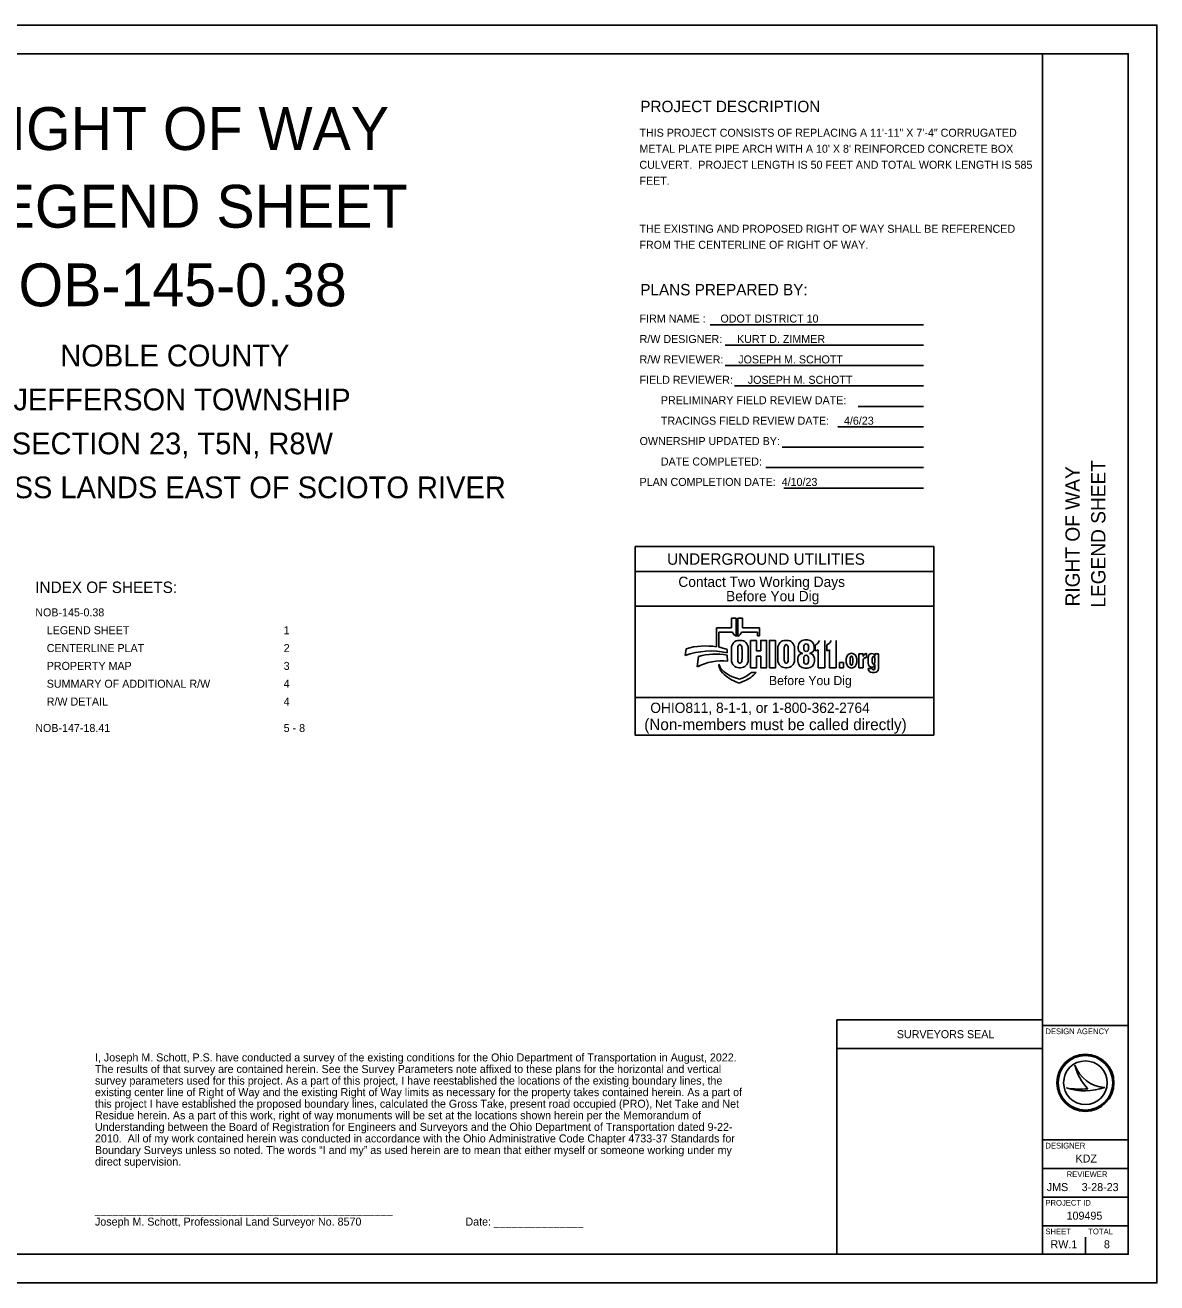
# Model space of a CAD drawing. Extents: x 0 to 34, y 0 to 22.
# Drawn here: x 14.2 to 34, y 0 to 22 of the extents above; entities that cross this region are included whole.
import ezdxf

# ---------------------------------------------------------------- set-up
doc = ezdxf.new("R2010")
doc.units = 0
for name, color, linetype in [('SH_Border', 7, 'Continuous'), ('SH_Cut_Line', 7, 'Continuous'), ('SH_Data', 7, 'Continuous'), ('SH_Text', 7, 'Continuous')]:
    doc.layers.add(name, color=color, linetype=linetype)

msp = doc.modelspace()

# ---------------------------------------------------------------- linework, layer by layer
at = {"layer": 'SH_Border'}
for p, q in [((32, 0.5), (32, 21.5)), ((32, 4.5), (33.5, 4.5)), ((32, 2.5), (33.5, 2.5)), ((32, 2), (33.5, 2)), ((32, 1.5), (33.5, 1.5)), ((32, 1), (33.5, 1))]:
    msp.add_line(p, q, dxfattribs=at)
msp.add_lwpolyline([(1.5, 21.5), (33.5, 21.5), (33.5, 0.5), (1.5, 0.5)], close=True, dxfattribs=at)
at = {"layer": 'SH_Cut_Line'}
msp.add_lwpolyline([(0, 0), (34, 0), (34, 22), (0, 22)], close=True, dxfattribs=at)
at = {"layer": 'SH_Data'}
for p, q in [((26.559, 11.46), (26.296, 11.46)), ((26.296, 11.46), (26.296, 11.125)), ((26.639, 11.626), (26.559, 11.626)), ((26.559, 11.626), (26.559, 11.46)), ((26.639, 11.309), (26.639, 11.626)), ((26.75, 11.626), (26.67, 11.626)), ((26.67, 11.626), (26.67, 11.309)), ((26.75, 11.46), (26.75, 11.626)), ((27.048, 11.46), (26.75, 11.46)), ((27.048, 11.319), (27.048, 11.46)), ((26.334, 11.119), (26.334, 11.383)), ((26.334, 11.383), (26.574, 11.383)), ((26.716, 11.238), (26.691, 11.238)), ((26.735, 11.383), (27.013, 11.383)), ((26.993, 11.237), (26.892, 11.237)), ((26.892, 11.237), (26.892, 10.759)), ((27.013, 11.383), (27.013, 11.319)), ((27.013, 11.319), (27.048, 11.319)), ((27.526, 11.238), (27.502, 11.238)), ((27.887, 11.245), (27.839, 11.245)), ((28.191, 11.237), (28.191, 10.759)), ((28.391, 11.237), (28.391, 10.759)), ((25.761, 11.091), (25.747, 10.974)), ((26.48, 11.023), (26.48, 11.081)), ((26.557, 11.105), (26.557, 10.893)), ((26.666, 10.91), (26.666, 11.092)), ((26.741, 11.092), (26.741, 10.91)), ((26.849, 10.893), (26.849, 11.105)), ((27.368, 11.105), (27.368, 10.893)), ((27.477, 10.91), (27.477, 11.092)), ((27.551, 11.092), (27.551, 10.91)), ((27.66, 10.893), (27.66, 11.105)), ((27.725, 11.131), (27.725, 11.095)), ((27.823, 11.078), (27.823, 11.136)), ((27.904, 11.136), (27.904, 11.078)), ((28.001, 11.095), (28.001, 11.131)), ((28.024, 11.057), (28.024, 11.158)), ((28.073, 10.759), (28.073, 11.071)), ((28.225, 11.057), (28.225, 11.158)), ((28.273, 10.759), (28.273, 11.071)), ((28.86, 11.002), (28.787, 11.002)), ((28.787, 11.002), (28.787, 10.759)), ((28.86, 10.955), (28.86, 11.002)), ((28.921, 11.01), (28.915, 11.01)), ((28.921, 10.936), (28.921, 11.01)), ((29.064, 10.957), (29.064, 11.004)), ((29.064, 11.004), (29.129, 11.004)), ((29.129, 11.004), (29.129, 10.745)), ((25.981, 10.956), (25.959, 10.776)), ((26.333, 10.819), (26.337, 10.792)), ((26.49, 10.873), (26.481, 10.979)), ((26.993, 10.759), (26.993, 10.961)), ((27.719, 10.925), (27.719, 10.874)), ((27.82, 10.865), (27.82, 10.926)), ((27.905, 10.926), (27.905, 10.865)), ((28.007, 10.874), (28.007, 10.925)), ((28.565, 10.85), (28.565, 10.918)), ((28.632, 10.849), (28.632, 10.918)), ((28.68, 10.918), (28.68, 10.849)), ((28.748, 10.918), (28.748, 10.85)), ((28.86, 10.759), (28.86, 10.886)), ((28.909, 10.936), (28.921, 10.936)), ((28.949, 10.837), (28.949, 10.941)), ((29.021, 10.851), (29.021, 10.927)), ((29.064, 10.927), (29.064, 10.851)), ((29.064, 10.745), (29.064, 10.815)), ((26.698, 10.558), (26.609, 10.589)), ((26.691, 10.759), (26.716, 10.759)), ((26.759, 10.585), (26.698, 10.558)), ((26.892, 10.759), (26.993, 10.759)), ((26.991, 10.679), (26.905, 10.679)), ((26.989, 10.676), (26.991, 10.679)), ((27.502, 10.759), (27.526, 10.759)), ((27.84, 10.753), (27.887, 10.753)), ((28.191, 10.759), (28.073, 10.759)), ((28.391, 10.759), (28.273, 10.759)), ((28.787, 10.759), (28.86, 10.759)), ((28.949, 10.745), (29.021, 10.745)), ((29.059, 10.676), (29.019, 10.676)), ((26.633, 10.512), (26.689, 10.488)), ((26.689, 10.488), (26.783, 10.529)), ((30.095, 9.581), (24.87, 9.581)), ((28.4, 4.1), (32, 4.1)), ((32.567, 3.81), (32.567, 3.81)), ((32.417, 3.41), (32.417, 3.41)), ((32.75, 3.5), (32.75, 3.5)), ((33.087, 3.419), (33.087, 3.419)), ((32.375, 0.675), (32.375, 0.675)), ((32.75, 0.5), (32.75, 0.8))]:
    msp.add_line(p, q, dxfattribs=at)
for points in [[(24.87, 12.881), (30.095, 12.881), (30.095, 12.441), (24.87, 12.441)], [(24.87, 12.441), (30.095, 12.441), (30.095, 11.836), (24.87, 11.836)], [(24.87, 11.836), (30.095, 11.836), (30.095, 10.241), (24.87, 10.241)], [(28.449, 10.849), (28.515, 10.849), (28.515, 10.759), (28.449, 10.759)], [(24.87, 10.241), (30.095, 10.241), (30.095, 9.581), (24.87, 9.581)], [(28.4, 4.6), (32, 4.6), (32, 0.5), (28.4, 0.5)]]:
    msp.add_lwpolyline(points, close=True, dxfattribs=at)
for points in [[(26.993, 10.961), (27.07, 10.961), (27.07, 10.759), (27.171, 10.759), (27.171, 11.237), (27.07, 11.237), (27.07, 11.057), (26.993, 11.057), (26.993, 11.237)], [(27.222, 10.759), (27.325, 10.759), (27.325, 11.237), (27.222, 11.237), (27.222, 10.759)], [(27.805, 11.011), (27.805, 11.011)], [(27.921, 11.011), (27.921, 11.011)]]:
    msp.add_lwpolyline(points, dxfattribs=at)
for radius in [0.5, 0.477, 0.477, 0.382]:
    msp.add_circle((32.75, 3.5), radius, dxfattribs=at)
for centre, radius, start, end in [((26.691, 11.105), 0.134, 90, 180), ((26.711, 11.438), 0.147, 201.9296, 240.7469), ((26.598, 11.438), 0.147, 299.2531, 338.0704), ((26.716, 11.105), 0.134, 0, 90), ((27.502, 11.105), 0.134, 90, 180), ((27.526, 11.105), 0.134, 0, 90), ((27.839, 11.131), 0.114, 90, 180), ((27.887, 11.131), 0.114, 0, 90), ((27.974, 11.281), 0.132, 292.5572, 340.7355), ((28.174, 11.281), 0.132, 292.5572, 340.7355), ((26.199, 9.721), 1.332, 77.8238, 109.8274), ((26.105, 9.917), 1.224, 81.0007, 106.3144), ((26.105, 9.917), 1.224, 72.1402, 79.2074), ((27.805, 10.925), 0.0865, 90, 180), ((27.808, 11.095), 0.0837, 180, 268.1442), ((27.918, 11.095), 0.0837, 272.2058, 0), ((27.921, 10.925), 0.0865, 0, 90), ((28.013, 11.188), 0.132, 275.1733, 297.0931), ((28.213, 11.188), 0.132, 275.1733, 297.0931), ((28.661, 10.918), 0.0956, 92.5886, 180), ((28.652, 10.918), 0.0956, 0, 87.4114), ((28.915, 10.955), 0.0548, 90, 180), ((29.018, 10.941), 0.0686, 92.6865, 180), ((29.012, 10.957), 0.0524, 0, 86.9262), ((26.388, 9.929), 0.95, 83.8248, 116.8021), ((26.28, 9.904), 1.094, 79.44, 105.8467), ((26.613, 10.927), 0.3, 201.0457, 232.5314), ((26.548, 10.828), 0.214, 189.6817, 216.0884), ((26.691, 10.893), 0.134, 180, 270), ((26.716, 10.893), 0.134, 270, 0), ((27.502, 10.893), 0.134, 180, 270), ((27.526, 10.893), 0.134, 270, 0), ((27.84, 10.874), 0.121, 180, 270), ((27.887, 10.874), 0.121, 270, 0), ((28.661, 10.85), 0.0956, 180, 267.4114), ((28.652, 10.85), 0.0956, 272.5886, 0), ((28.909, 10.886), 0.0493, 90, 180), ((29.018, 10.837), 0.0692, 180, 265.7132), ((29.017, 10.815), 0.0467, 264.7825, 0), ((26.748, 10.974), 0.461, 216.0884, 235.7167), ((26.9, 11.302), 0.773, 232.5314, 241.794), ((26.997, 11.339), 0.903, 235.7167, 246.2325), ((26.773, 11.065), 0.504, 241.794, 250.9821), ((26.545, 11.078), 0.538, 293.4582, 312.0712), ((26.545, 11.078), 0.599, 293.4582, 317.8286), ((29.019, 10.745), 0.0699, 180, 270), ((29.059, 10.745), 0.0699, 270, 0), ((33.116, 3.998), 0.58, 198.9257, 198.9319), ((33.347, 3.97), 0.796, 191.6379, 191.6421), ((33.116, 3.998), 0.58, 198.9319, 267.1657), ((33.347, 3.97), 0.796, 191.6421, 226.0947), ((32.739, 4.37), 1.013, 251.4576, 290.0832), ((32.648, 4.654), 1.266, 259.4964, 259.4995), ((32.739, 4.37), 1.013, 251.4527, 251.4576), ((32.648, 4.654), 1.266, 259.4995, 276.6672)]:
    msp.add_arc(centre, radius, start, end, dxfattribs=at)
for centre, major_axis, ratio, start_param, end_param in [((26.703, 11.092), (0, 0.0723), 0.514403, 4.712389, 7.853982), ((27.514, 11.092), (0, 0.0723), 0.514403, 4.712389, 7.853982), ((27.864, 11.136), (0.0404, 0), 0.969373, 0, 3.141593), ((27.864, 11.078), (0.0404, 0), 0.818453, 3.141593, 6.283185), ((26.703, 10.91), (0, 0.0723), 0.514403, 1.570796, 4.712389), ((27.514, 10.91), (0, 0.0723), 0.514403, 1.570796, 4.712389), ((27.862, 10.926), (0, 0.0535), 0.794529, 4.712389, 7.853982), ((27.862, 10.865), (0.0425, 0), 0.959837, 3.141593, 6.283185), ((28.656, 10.918), (0, 0.0434), 0.553236, 4.712389, 7.853982), ((28.656, 10.849), (0, 0.046), 0.522014, 1.570796, 4.712389), ((29.043, 10.927), (0, 0.0275), 0.777179, 4.712389, 7.853982), ((29.043, 10.851), (0, 0.0275), 0.777179, 1.570796, 4.712389), ((29.043, 10.745), (0.0214, 0), 0.959012, 3.141593, 6.283185)]:
    msp.add_ellipse(centre, major_axis=major_axis, ratio=ratio, start_param=start_param, end_param=end_param, dxfattribs=at)
at = {"layer": 'SH_Text'}
for p, q in [((26.181, 16.76), (29.918, 16.76)), ((26.445, 16.403), (29.918, 16.403)), ((26.445, 16.046), (29.918, 16.046)), ((26.609, 15.689), (29.918, 15.689)), ((28.773, 15.331), (29.918, 15.331)), ((28.415, 14.974), (29.918, 14.974)), ((27.445, 14.617), (29.918, 14.617)), ((27.16, 14.26), (29.918, 14.26)), ((27.475, 13.903), (29.918, 13.903))]:
    msp.add_line(p, q, dxfattribs=at)

# ---------------------------------------------------------------- texts
at = {"layer": 'SH_Data'}
for s, height, p in [('RIGHT OF WAY', 0.75, (13.21, 19.816)), ('LEGEND SHEET', 0.75, (13.141, 18.457)), ('NOB-145-0.38', 0.75, (13.358, 17.082)), ('NOBLE COUNTY', 0.38, (14.813, 16.03)), ('JEFFERSON TOWNSHIP', 0.38, (13.993, 15.262)), ('SECTION 23, T5N, R8W', 0.38, (13.964, 14.493)), ('CONGRESS LANDS EAST OF SCIOTO RIVER', 0.38, (11.765, 13.725)), ('UNDERGROUND UTILITIES', 0.2, (25.43, 12.561)), ('Contact Two Working Days', 0.18, (25.627, 12.173)), ('INDEX OF SHEETS:', 0.2, (14.375, 12.067)), ('Before You Dig', 0.18, (26.462, 11.923)), ('NOB-145-0.38', 0.14, (14.375, 11.658)), ('LEGEND SHEET', 0.14, (14.575, 11.346)), ('1', 0.14, (18.721, 11.346)), ('CENTERLINE PLAT', 0.14, (14.575, 11.034)), ('2', 0.14, (18.721, 11.034)), ('PROPERTY MAP', 0.14, (14.575, 10.722)), ('3', 0.14, (18.721, 10.722)), ('Before You Dig', 0.15972, (27.213, 10.456)), ('SUMMARY OF ADDITIONAL R/W', 0.14, (14.575, 10.41)), ('4', 0.14, (18.721, 10.41)), ('R/W DETAIL', 0.14, (14.575, 10.098)), ('4', 0.14, (18.721, 10.098)), ('OHIO811, 8-1-1, or 1-800-362-2764', 0.18, (25.136, 9.969)), ('NOB-147-18.41', 0.14, (14.375, 9.636)), ('5 - 8', 0.14, (18.721, 9.636)), ('(Non-members must be called directly)', 0.2, (25.03, 9.668)), ('SURVEYORS SEAL', 0.14, (29.45, 4.28)), ('DESIGN AGENCY', 0.1, (32.05, 4.35)), ('DESIGNER', 0.1, (32.05, 2.35)), ('KDZ', 0.14, (32.577, 2.105)), ('REVIEWER', 0.1, (32.422, 1.85)), ('JMS', 0.14, (32.074, 1.605)), ('3-28-23', 0.14, (32.685, 1.605)), ('PROJECT ID', 0.1, (32.05, 1.35)), ('109495', 0.14, (32.421, 1.105)), ('SHEET', 0.1, (32.05, 0.85)), ('TOTAL', 0.1, (32.8, 0.85)), ('RW.1', 0.14, (32.14, 0.605)), ('8', 0.14, (33.074, 0.605))]:
    msp.add_text(s, height=height, dxfattribs=at).set_placement(p)
for s, p in [('LEGEND SHEET', (33.1, 11.81)), ('RIGHT OF WAY', (32.65, 11.832))]:
    msp.add_text(s, height=0.25, rotation=90, dxfattribs=at).set_placement(p)
at = {"layer": 'SH_Text'}
for s, height, p in [('PROJECT DESCRIPTION', 0.2, (24.961, 20.478)), ('THIS PROJECT CONSISTS OF REPLACING A 11\'-11" X 7\'-4" CORRUGATED ', 0.14, (24.946, 20.048)), ("METAL PLATE PIPE ARCH WITH A 10' X 8' REINFORCED CONCRETE BOX ", 0.14, (24.946, 19.768)), ('CULVERT.  PROJECT LENGTH IS 50 FEET AND TOTAL WORK LENGTH IS 585 ', 0.14, (24.946, 19.488)), ('FEET.', 0.14, (24.946, 19.208)), ('THE EXISTING AND PROPOSED RIGHT OF WAY SHALL BE REFERENCED ', 0.14, (24.946, 18.368)), ('FROM THE CENTERLINE OF RIGHT OF WAY.', 0.14, (24.946, 18.088)), ('PLANS PREPARED BY:', 0.2, (24.961, 17.273)), ('FIRM NAME :     ODOT DISTRICT 10', 0.14, (24.949, 16.797)), ('R/W DESIGNER:     KURT D. ZIMMER', 0.14, (24.949, 16.44)), ('R/W REVIEWER:     JOSEPH M. SCHOTT', 0.14, (24.949, 16.083)), ('FIELD REVIEWER:     JOSEPH M. SCHOTT', 0.14, (24.949, 15.726)), ('PRELIMINARY FIELD REVIEW DATE:', 0.14, (25.321, 15.369)), ('TRACINGS FIELD REVIEW DATE:     4/6/23      ', 0.14, (25.321, 15.011)), ('OWNERSHIP UPDATED BY:', 0.14, (24.949, 14.655)), ('DATE COMPLETED:', 0.14, (25.321, 14.297)), ('PLAN COMPLETION DATE:  4/10/23', 0.14, (24.949, 13.94)), ('I, Joseph M. Schott, P.S. have conducted a survey of the existing conditions for the Ohio Department of Transportation in August, 2022. ', 0.14, (15.419, 3.873)), ('The results of that survey are contained herein. See the Survey Parameters note affixed to these plans for the horizontal and vertical ', 0.14, (15.419, 3.671)), ('survey parameters used for this project. As a part of this project, I have reestablished the locations of the existing boundary lines, the ', 0.14, (15.419, 3.468)), ('existing center line of Right of Way and the existing Right of Way limits as necessary for the property takes contained herein. As a part of ', 0.14, (15.419, 3.266)), ('this project I have established the proposed boundary lines, calculated the Gross Take, present road occupied (PRO), Net Take and Net ', 0.14, (15.419, 3.063)), ('Residue herein. As a part of this work, right of way monuments will be set at the locations shown herein per the Memorandum of ', 0.14, (15.419, 2.861)), ('Understanding between the Board of Registration for Engineers and Surveyors and the Ohio Department of Transportation dated 9-22-', 0.14, (15.419, 2.658)), ('2010.  All of my work contained herein was conducted in accordance with the Ohio Administrative Code Chapter 4733-37 Standards for ', 0.14, (15.419, 2.456)), ('Boundary Surveys unless so noted. The words “I and my” as used herein are to mean that either myself or someone working under my ', 0.14, (15.419, 2.253)), ('direct supervision.', 0.14, (15.419, 2.051)), ('__________________________________________________', 0.14, (15.419, 1.211)), ('Joseph M. Schott, Professional Land Surveyor No. 8570                                   Date: _______________                  ', 0.14, (15.419, 1.001))]:
    msp.add_text(s, height=height, dxfattribs=at).set_placement(p)

doc.saveas('drawing.dxf')
